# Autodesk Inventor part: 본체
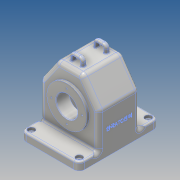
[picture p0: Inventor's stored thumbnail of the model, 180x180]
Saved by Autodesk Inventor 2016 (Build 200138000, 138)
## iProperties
Created: 2016-12
Part Number: 본체
Material: 알루미늄 6061
Document SubType Name: Modeling
Designer: Administrator
Density: 2.7 g/cm^3
Appearance: 알루미늄 - 평지
Mass: 1055.25 g
Surface Area: 1145.79 cm^2
Volume: 390.833 cm^3
Author: Administrator
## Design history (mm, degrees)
sketch "스케치1"
  geometry: L1 (-75, 55)-(75, 55); L2 (75, 55)-(75, -55); L3 (75, -55)-(-75, -55); L4 (-75, -55)-(-75, 55); 3 further points
  constraints: 8 end point, 2 midpoint, 2 parallel, 1 horizontal, 1 horizontal alignment, 1 perpendicular, 1 vertical alignment
  dimensions: "d0" = 150 distance between parallel lines of L2 L4; "d1" = 110 distance between parallel lines of L3 L1
extrude "돌출1" new body sketch "스케치1" distance "d2" = 15; taper "d3" = 0 deg
fillet "모깎기1" dims "d4" = 10
sketch "스케치3"
  geometry: A1 r 10 centre (65, 45) between (75, 45) and (65, 55) reference; A2 r 10 centre (-65, 45) between (-65, 55) and (-75, 45) reference; A3 r 10 centre (-65, -45) between (-75, -45) and (-65, -55) reference; A4 r 10 centre (65, -45) between (65, -55) and (75, -45) reference; 5 further points
  constraints: 4 coincident
hole "구멍1" sketch "스케치3" at (-65, 45), (65, 45), (65, -45), (-65, -45) diameter "d5" = 5; stored, may be unused: countersink angle "d9" = 90 deg, drill point angle "d11" = 0 deg; dims "d6" = 6, "d7" = 12, "d8" = 5, "d10" = 8
sketch "스케치4"
  geometry: L1 (-55, 0)-(-55, 15) reference; L2 (55, 15)-(55, 0) reference; L3 (45, 15)-(55, 15) reference; L4 (-51, 15)-(-39, 15) reference; L5 (-55, 15)-(-45, 15) reference; L6 (-55, 0)-(-55, 80); L7 (-55, 80)-(55, 80); L8 (55, 0)-(45, 0) reference; L9 (55, 80)-(55, 0); L10 (-55, 80)-(-23.491, 125); L11 (-23.491, 125)-(23.491, 125); L12 (23.491, 125)-(55, 80); L13 (-45, 0)-(45, 0) reference; L14 (-55, 0)-(55, 0); 1 further point
  constraints: 14 end point, 2 horizontal, 2 perpendicular, 1 vertical
  dimensions: "d12" = 80 distance of L1.start L6.end; "d13" = 35 deg angle of L10 L6; "d14" = 35 deg angle of L9 L12; "d15" = 125 distance between parallel lines of L11 L13
extrude "돌출2" join sketch "스케치4" stored distance "d16" = 77; taper "d17" = 0 deg
sketch "스케치9"
  geometry: L1 (50, 0)-(50, 78.424); L2 (20.888, 120)-(-20.888, 120); L3 (-50, 78.424)-(-50, 0); L4 (-50, 0)-(50, 0); L5 (55, 15)-(-55, 15) reference; L6 (55, 15)-(55, 80) reference; L7 (55, 80)-(23.491, 125) reference; L8 (23.491, 125)-(-23.491, 125) reference; L9 (-23.491, 125)-(-55, 80) reference; L10 (-55, 80)-(-55, 15) reference; L11 (20.888, 120)-(50, 78.424); L12 (-20.888, 120)-(-50, 78.424); 3 further points
  constraints: 12 end point, 3 parallel, 2 midpoint, 2 perpendicular, 1 coincident, 1 vertical, 1 vertical alignment
  dimensions: "d34" = 5 distance between parallel lines of L8 L2; "d35" = 5 distance between parallel lines of L6 L1; "d112" = 5 distance between parallel lines of L11 L7; "d115" = 5 distance between parallel lines of L9 L12; "d116" = 5 distance between parallel lines of L10 L3
extrude "돌출4" cut sketch "스케치9" stored distance "d36" = 67; taper "d37" = 0 deg
sketch "스케치10"
  geometry: L1 (43.5, 65)-(-48.5, 65); L2 (38.5, 80)-(38.5, 15) reference; L3 (43.5, 85)-(43.5, 102.5); L4 (-48.5, 85)-(-48.5, 96); L5 (-48.5, 96)-(-33.5, 96); L6 (-33.5, 96)-(-33.5, 85); L7 (-33.5, 0)-(-33.5, 78.424) reference; L8 (-33.5, 85)-(-48.5, 85); L9 (19.5, 92)-(19.5, 85); L10 (19.5, 85)-(43.5, 85); L11 (19.5, 92)-(30, 102.5); L12 (30, 102.5)-(43.5, 102.5); 2 further points
  constraints: 20 end point, 4 vertical, 3 horizontal, 2 perpendicular, 2 vertical alignment
  dimensions: "d38" = 92 distance of L1.start L1.end; "d39" = 5 distance from line of L2 L1.start; "d40" = 65 distance from line of point (0, 0) L1; "d45" = 15 distance between parallel lines of L4 L6; "d46" = 62 diameter of L5 L1; "d50" = 24 distance between parallel lines of L9 L3; "d51" = 40 diameter of L10 L1; "d53" = 40 diameter of L8 L1; "d106" = 54 diameter of L9.start L1; "d107" = 45 deg angle of L11 L9; "d108" = 75 diameter of L12 L1
revolve "회전1" sketch "스케치10" stored, may be unused: angle "d47" = 90 deg
sketch "스케치11"
  geometry: C1 r 20 at (0, 0) reference; C2 r 37.5 at (0, 0) reference; C3 r 20 at (0, 0); 1 further point
  constraints: 1 centre point, 1 coincident, 1 concentric
extrude "돌출5" cut sketch "스케치11" stored distance "d48" = 67; taper "d49" = 0 deg
node "작업 평면1"
sketch "스케치14"
  geometry: L1 (-23.491, 125)-(23.491, 125) reference; L2 (0, 125)-(0, 140); L3 (-12.5, 140)-(12.5, 140); L4 (12.5, 140)-(12.5, 125); L5 (-12.5, 140)-(-12.5, 125); L6 (-7.5, 125)-(-7.5, 135); L7 (-7.5, 135)-(7.5, 135); L8 (7.5, 135)-(7.5, 125); 6 further points
  constraints: 14 end point, 8 point on line, 5 midpoint, 3 perpendicular, 3 vertical, 3 vertical alignment, 1 horizontal
  dimensions: "d57" = 25 distance between parallel lines of L4 L5; "d58" = 140 distance from line of L3 point (0, 0); "d64" = 5 distance between parallel lines of L3 L7; "d93" = 15 distance between parallel lines of L8 L6
extrude "돌출6" join sketch "스케치14" distance "d65" = 8; taper "d66" = 0 deg
fillet "모깎기2" dims "d67" = 1
sketch "스케치17"
  geometry: C1 r 20 at (0, 0) reference; C2 r 31 at (0, 0) reference; A1 r 26 centre (0, 0) between (-26, 0) and (0, 26); 3 further points
  constraints: 4 point on circle, 2 horizontal alignment, 2 vertical alignment, 1 centre point, 1 coincident
  dimensions: "d68" = 52 diameter of A1
hole "구멍2" sketch "스케치17" at (-26, 0), (0, 26), (26, 0), (0, -26) diameter "d69" = 2.459; stored, may be unused: countersink angle "d73" = 90 deg, drill point angle "d75" = 118 deg; dims "d70" = 6, "d71" = 12, "d72" = 5, "d74" = 8
node "작업 평면3"
sketch "스케치19"
  geometry: L1 (-103.5, 15)-(-103.5, 80) reference; 2 further points
  constraints: 1 other
  dimensions: "d76" = 45 distance of point (-65, 45) point (-65, 0); "d77" = 38.5 distance from line of point (-65, 45) L1
feature "엠보싱1" sketch "스케치19" dims "d0" = 150, "d1" = 110, "d78" = 0.5, "d79" = 0
sketch "스케치21"
  geometry: C1 r 20 at (0, 0) reference; C2 r 37.5 at (0, 0) reference; A1 r 29 centre (0, 0) between (29, 0) and (0, -29); 3 further points
  constraints: 4 point on circle, 2 horizontal alignment, 2 vertical alignment, 1 centre point, 1 coincident
  dimensions: "d80" = 58 diameter of A1
hole "구멍3" sketch "스케치21" at (29, 0), (0, -29), (-29, 0), (0, 29) diameter "d81" = 2.459; stored, may be unused: countersink angle "d85" = 90 deg, drill point angle "d87" = 118 deg; dims "d82" = 6, "d83" = 12, "d84" = 5, "d86" = 8
fillet "모깎기3" dims "d88" = 3
fillet "모깎기4" dims "d89" = 3
fillet "모깎기5" dims "d90" = 3
fillet "모깎기6" dims "d91" = 3
fillet "모깎기8" dims "d94" = 8
fillet "모깎기9" dims "d95" = 3
fillet "모깎기10" dims "d96" = 1
fillet "모깎기15" dims "d101" = 3
fillet "모깎기16" dims "d102" = 3
chamfer "모따기1" distance "d103" = 1; stored, may be unused: second distance "d104" = 2, angle "d105" = 45 deg
fillet "모깎기18" dims "d110" = 10
fillet "모깎기19" dims "d111" = 8
node "솔리드1"
mirror "대칭4"
node "투영된 루프1"
other parameters: "d54" = 18, "d114" = 5
